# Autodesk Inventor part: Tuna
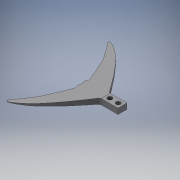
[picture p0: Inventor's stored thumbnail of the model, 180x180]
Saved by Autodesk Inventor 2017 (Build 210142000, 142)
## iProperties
Part Number: Tuna
Material: Genérico
Document SubType Name: Modeling
Designer: Diego
Density: 1 g/cm^3
Appearance: Valor por defecto
Author: Diego
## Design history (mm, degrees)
sketch "Boceto1"
  geometry: L1 (-69.404, 62.222)-(212.818, 62.222); L2 (212.818, 62.222)-(212.818, -58.781); L3 (212.818, -58.781)-(-69.404, -58.781); L4 (-69.404, -58.781)-(-69.404, 62.222); L5 (0, 0)-(-152.638, 0); L6 (-105.395, -3.178)-(-107.874, -5.918); L7 (-107.874, -5.918)-(-110.484, -9.964); L8 (-110.484, -9.964)-(-114.138, -14.401); L9 (-114.138, -14.401)-(-116.748, -18.185); L10 (-116.748, -18.185)-(-121.838, -24.449); L11 (-121.838, -24.449)-(-128.102, -31.496); L12 (-128.102, -31.496)-(-131.103, -34.759); L13 (-131.103, -34.759)-(-134.757, -38.282); L14 (-134.757, -38.282)-(-140.108, -42.067); L15 (-140.108, -42.067)-(-143.37, -44.416); L16 (-143.37, -44.416)-(-147.285, -46.243); L17 (-147.285, -46.243)-(-148.721, -46.243); L18 (-148.721, -46.243)-(-149.66, -46.509); L19 (-126.619, 0)-(-126.247, -1.313); L20 (-126.247, -1.313)-(-127.266, -1.789); L21 (-127.266, -1.789)-(-127.548, -2.501); L22 (-127.548, -2.501)-(-127.192, -3.651); L23 (-127.192, -3.651)-(-126.619, -4.992); L24 (-126.619, -4.992)-(-126.187, -6.091); L25 (-126.187, -6.091)-(-126.619, -7.499); L26 (-126.619, -7.499)-(-127.572, -9.615); L27 (-127.572, -9.615)-(-128.744, -11.973); L28 (-128.744, -11.973)-(-129.245, -13.843); L29 (-129.245, -13.843)-(-132.194, -19.75); L30 (-132.194, -19.75)-(-133.973, -23.852); L31 (-133.973, -23.852)-(-136.453, -28.959); L32 (-136.453, -28.959)-(-138.426, -31.819); L33 (-138.426, -31.819)-(-140.236, -33.82); L34 (-140.236, -33.82)-(-144.662, -40.68); L35 (-144.662, -40.68)-(-147.161, -43.442); L36 (-147.161, -43.442)-(-149.004, -45.245); L37 (-149.004, -45.245)-(-149.66, -46.509); L38 (-105.395, -3.178)-(-105.395, 0); L39 (-126.619, 0)-(-126.247, 1.313); L40 (-126.247, 1.313)-(-127.266, 1.789); L41 (-127.266, 1.789)-(-127.548, 2.501); L42 (-127.548, 2.501)-(-127.192, 3.651); L43 (-127.192, 3.651)-(-126.619, 4.992); L44 (-126.619, 4.992)-(-126.187, 6.091); L45 (-126.187, 6.091)-(-126.619, 7.499); L46 (-126.619, 7.499)-(-127.572, 9.615); L47 (-127.572, 9.615)-(-128.744, 11.973); L48 (-128.744, 11.973)-(-129.245, 13.843); L49 (-129.245, 13.843)-(-132.194, 19.75); L50 (-132.194, 19.75)-(-133.973, 23.852); L51 (-133.973, 23.852)-(-136.453, 28.959); L52 (-136.453, 28.959)-(-138.426, 31.819); L53 (-138.426, 31.819)-(-140.236, 33.82); L54 (-140.236, 33.82)-(-144.662, 40.68); L55 (-144.662, 40.68)-(-147.161, 43.442); L56 (-147.161, 43.442)-(-149.004, 45.245); L57 (-149.004, 45.245)-(-149.66, 46.509); L58 (-105.395, 3.178)-(-107.874, 5.918); L59 (-107.874, 5.918)-(-110.484, 9.964); L60 (-110.484, 9.964)-(-114.138, 14.401); L61 (-114.138, 14.401)-(-116.748, 18.185); L62 (-116.748, 18.185)-(-121.838, 24.449); L63 (-121.838, 24.449)-(-128.102, 31.496); L64 (-128.102, 31.496)-(-131.103, 34.759)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; 1 other entity
  constraints: 32 symmetric about line, 6 end point, 2 horizontal, 2 point on line, 1 vertical, 14 other
extrude "Extrusión1" new body sketch "Boceto1" stored distance "d7" = 5; taper "d8" = 0 deg
sketch "Boceto2"
  geometry: L1 (5, 6.355)-(5, 0) reference; L2 (0, 0)-(0, 6.355) reference; L3 (0, 6.355)-(5, 6.355) reference; L4 (5, 0)-(0, 0) reference; 2 further points
  constraints: 1 coincident, 3 other
node "Plano de trabajo1"
node "Plano de trabajo2"
sketch "Boceto3"
  geometry: C1 r 7.5 at (2.5, 3.178); 2 further points
  constraints: 1 centre point, 1 coincident
  dimensions: "d11" = 15 diameter of C1
sketch "Boceto4"
  geometry: L1 (5, 12.778)-(5, -6.422) reference; L2 (0, -6.422)-(0, 12.778) reference; C1 r 2.5 at (2.5, 3.178); 2 further points
  constraints: 2 horizontal alignment, 1 centre point, 1 coincident, 1 tangent
feature "Solevación1" sketch "Boceto3", "Boceto4" dims "d12" = 0, "d13" = 90 deg, "d14" = 0, "d15" = 90 deg, "d16" = 0, "d17" = 90 deg
sketch "Boceto5"
  geometry: 3 further points
  constraints: 1 horizontal alignment
extrude "Extrusión2" new body sketch "Boceto5" distance "d18" = 3; taper "d19" = 0 deg
fillet "Empalme1" dims "d20" = 1
node "Plano de trabajo3"
node "Plano de trabajo7"
sketch "Boceto11"
  geometry: L1 (-148.243, 42.741)-(-148.243, 46.551); 7 further points
  constraints: 2 end point, 2 vertical, 1 point on line, 2 other
node "Plano de trabajo8"
feature "Dividir4"
mirror "Simetría1"
feature "Dividir5"
sketch "Boceto12"
  geometry: L1 (5, -0.822)-(0, -0.822); L2 (0, -0.822)-(0, 7.178); L3 (0, 7.178)-(5, 7.178); L4 (5, 7.178)-(5, -0.822); L5 (5, -0.822)-(0, 7.178); L6 (0, -0.822)-(5, 7.178); 1 further point
  constraints: 12 end point, 2 midpoint, 2 parallel, 1 horizontal, 1 perpendicular
  dimensions: "d37" = 5 distance of L2.end L3.end; "d38" = 8 distance of L1.end L2.end
extrude "Extrusión6" join sketch "Boceto12" distance "d39" = 15; taper "d40" = 0 deg
fillet "Empalme3" dims "d41" = 3
sketch "Boceto14"
  geometry: L1 (-15, 0)-(-15, 8) reference; L2 (-15, 0)-(0, 0) reference; L3 (0, 8)-(0, 0) reference; L4 (-15, 8)-(0, 8) reference; L5 (0, 0)-(0, 8) reference; L6 (0, 4)-(-15, 4); L7 (-7.5, 4)-(0, 4); L8 (-7.5, 4)-(-15, 4); C1 r 2 at (-3.75, 4); C2 r 2 at (-11.25, 4); 1 further point
  constraints: 6 end point, 5 midpoint, 2 centre point, 2 collinear
  dimensions: "d42" = 4 diameter of C1; "d43" = 4 diameter of C2
extrude "Extrusión7" cut sketch "Boceto14" distance "d44" = 15; taper "d45" = 0 deg
node "Sólido1"
node "Imagen1"
node "Sólido2"
node "Sólido3"
node "Plano de trabajo9"
node "Contorno proyectado5"
node "Proyectar aristas de corte1"
other parameters: "d9" = -5, "d10" = 5, "d23" = 1.3, "d36" = 0.15
